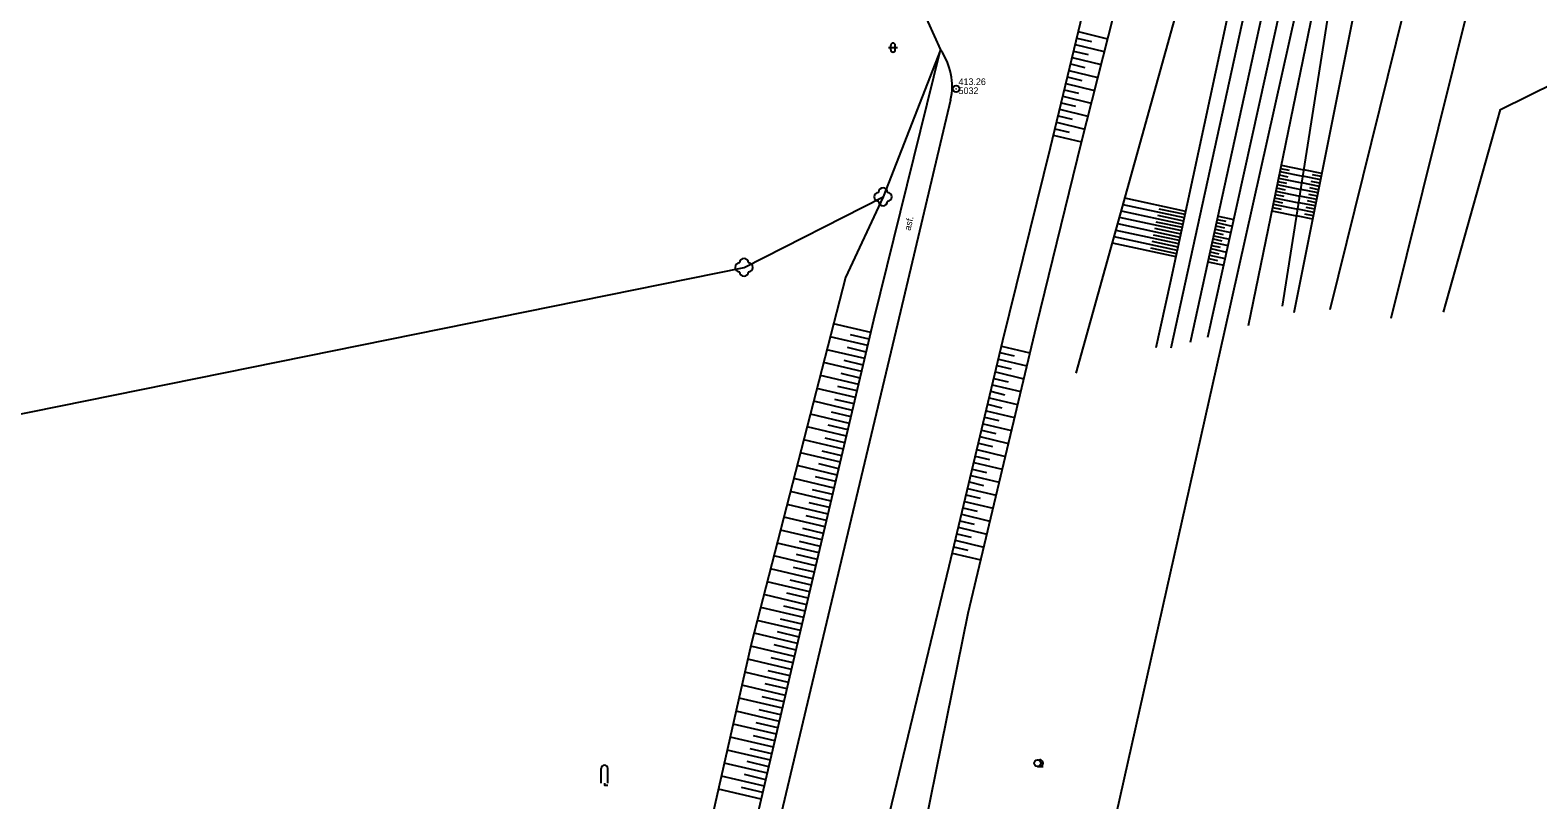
# Model space of a CAD drawing. Extents: x -737488 to -734267, y -1145775 to -1142573.
# Drawn here: x -734897.8 to -734727.9, y -1143098.1 to -1143011.4 of the extents above; entities that cross this region are included whole.
import ezdxf

# ---------------------------------------------------------------- set-up
doc = ezdxf.new("R2010")
doc.units = 0
for name, color, linetype in [('Vrstva 1', 7, 'Continuous'), ('Vrstva 10', 7, 'Continuous'), ('Vrstva 11', 7, 'Continuous'), ('Vrstva 12', 7, 'Continuous'), ('Vrstva 14', 7, 'Continuous'), ('Vrstva 19', 7, 'Continuous'), ('Vrstva 3', 7, 'Continuous'), ('Vrstva 9', 7, 'Continuous')]:
    doc.layers.add(name, color=color, linetype=linetype)

# ---------------------------------------------------------------- blocks, each defined once
blk = doc.blocks.new('1.079')
at = {"layer": 'Vrstva 1'}
for radius in [0.75, 0.001]:
    blk.add_circle((0, -0.001), radius, dxfattribs=at)
blk = doc.blocks.new('3.130')
at = {"layer": 'Vrstva 1'}
blk.add_circle((0, 0), 0.001, dxfattribs=at)
for centre, start, end in [((-1, 0), 90, 270), ((0, 1), 0, 180), ((1, 0), 270, 90), ((0, -1), 180, 360)]:
    blk.add_arc(centre, 1, start, end, dxfattribs=at)
blk = doc.blocks.new('3.100')
at = {"layer": 'Vrstva 1'}
for p, q in [((-0.75, 0), (-0.75, 3.25)), ((0.75, 0), (0.75, 3.25))]:
    blk.add_line(p, q, dxfattribs=at)
blk.add_lwpolyline([(0, 0), (0, -0.5), (0.75, -0.5)], dxfattribs=at)
blk.add_arc((0, 3.25), 0.75, 0, 180, dxfattribs=at)
blk = doc.blocks.new('3.110')
at = {"layer": 'Vrstva 1'}
blk.add_line((0, -0.75), (1.25, -0.75), dxfattribs=at)
blk.add_circle((0, 0), 0.75, dxfattribs=at)
blk.add_arc((0.5, 0), 0.75, 249.4944, 109.0474, dxfattribs=at)
blk = doc.blocks.new('3.160')
at = {"layer": 'Vrstva 1'}
for p, q in [((-1, 0), (1, 0)), ((-0.5, -0.5), (-0.5, 0.5)), ((0.5, -0.5), (0.5, 0.5))]:
    blk.add_line(p, q, dxfattribs=at)
for centre, start, end in [((0, 0.5), 0, 180), ((0, -0.5), 180, 360)]:
    blk.add_arc(centre, 0.5, start, end, dxfattribs=at)

msp = doc.modelspace()

# ---------------------------------------------------------------- linework, layer by layer
at = {"layer": 'Vrstva 10'}
for points in [[(-734751.34, -1143042.86), (-734739.27, -1142993.92), (-734731.29, -1142959.76)], [(-734744.49, -1143043.81), (-734732.04, -1142993.79), (-734723.59, -1142959.83)], [(-734782.88, -1143024.59), (-734776.82, -1142999.42)], [(-734799.53, -1143004.07), (-734795.25, -1143013.59)], [(-734802.76, -1143044), (-734795.25, -1143013.59)], [(-734794.12, -1143019.25), (-734800.11, -1143044.52)], [(-734788.23, -1143046.33), (-734782.88, -1143024.59)], [(-734811.45, -1143080.88), (-734802.76, -1143044)], [(-734800.11, -1143044.52), (-734808.87, -1143081.29)], [(-734794.3, -1143071.77), (-734788.23, -1143046.33)], [(-734800.43, -1143097.32), (-734794.3, -1143071.77)], [(-734821.67, -1143124.71), (-734811.45, -1143080.88)], [(-734808.87, -1143081.29), (-734819.27, -1143125.15)], [(-734806.53, -1143122.43), (-734800.43, -1143097.32)]]:
    msp.add_lwpolyline(points, dxfattribs=at)
msp.add_arc((-734801.12, -1143017.7), 7.17, 347.5402, 35.0408, dxfattribs=at)
at = {"layer": 'Vrstva 11'}
for points in [[(-734738.57, -1143043.16), (-734732.17, -1143020.29), (-734710.32, -1143009.52), (-734645.87, -1142991.4), (-734599.27, -1142980.03), (-734584.94, -1143004.15)], [(-734932.65, -1143097.27), (-734928.56, -1143060.61), (-734817.4, -1143038.1), (-734801.73, -1143030.15)]]:
    msp.add_lwpolyline(points, dxfattribs=at)
at = {"layer": 'Vrstva 12'}
for points in [[(-734779.96, -1143050.03), (-734764.08, -1142992.93), (-734756.15, -1142966.05), (-734753.33, -1142953.35)], [(-734770.94, -1143047.14), (-734769.33, -1143039.8), (-734750.72, -1142953.18)], [(-734767.1, -1143046.54), (-734757.95, -1143004.79), (-734746.58, -1142953.35)], [(-734765.15, -1143045.98), (-734756.07, -1143004.98), (-734744.15, -1142954.31)], [(-734760.57, -1143044.66), (-734752.72, -1143006.39), (-734741.14, -1142954.83)], [(-734756.74, -1143042.47), (-734751.11, -1143006.87), (-734739.76, -1142955.35)], [(-734755.41, -1143043.18), (-734747.78, -1143005.01), (-734735.87, -1142959.07)], [(-734779.39, -1143024), (-734770.86, -1142990.35)], [(-734779.74, -1143011.53), (-734776.43, -1143012.33)], [(-734795.25, -1143013.59), (-734801.73, -1143030.15), (-734805.97, -1143039.26)], [(-734780.26, -1143013.72), (-734778.62, -1143014.12)], [(-734780.09, -1143012.99), (-734776.8, -1143013.78)], [(-734779.91, -1143012.26), (-734778.26, -1143012.66)], [(-734780.62, -1143015.18), (-734778.98, -1143015.57)], [(-734780.44, -1143014.45), (-734777.17, -1143015.24)], [(-734780.97, -1143016.64), (-734779.34, -1143017.03)], [(-734780.79, -1143015.91), (-734777.54, -1143016.69)], [(-734781.49, -1143018.82), (-734778.27, -1143019.6)], [(-734781.32, -1143018.1), (-734779.7, -1143018.48)], [(-734781.14, -1143017.37), (-734777.91, -1143018.15)], [(-734781.84, -1143020.28), (-734778.64, -1143021.05)], [(-734781.67, -1143019.55), (-734780.06, -1143019.94)], [(-734782.19, -1143021.74), (-734779.01, -1143022.51)], [(-734782.02, -1143021.01), (-734780.42, -1143021.4)], [(-734784.45, -1143044.68), (-734779.39, -1143024)], [(-734782.55, -1143023.2), (-734779.38, -1143023.96)], [(-734782.37, -1143022.47), (-734780.78, -1143022.85)], [(-734757.01, -1143027.31), (-734754.43, -1143027.84)], [(-734756.94, -1143026.94), (-734755.96, -1143027.14)], [(-734756.86, -1143026.58), (-734754.31, -1143027.1)], [(-734752.28, -1143027.51), (-734754.31, -1143027.1)], [(-734757.39, -1143029.15), (-734756.41, -1143029.35)], [(-734757.31, -1143028.78), (-734754.66, -1143029.32)], [(-734757.24, -1143028.41), (-734756.26, -1143028.61)], [(-734757.16, -1143028.05), (-734754.54, -1143028.58)], [(-734757.09, -1143027.68), (-734756.11, -1143027.88)], [(-734752.57, -1143028.98), (-734754.54, -1143028.58)], [(-734752.42, -1143028.24), (-734754.43, -1143027.84)], [(-734752.65, -1143029.35), (-734753.63, -1143029.15)], [(-734752.5, -1143028.61), (-734753.48, -1143028.41)], [(-734752.35, -1143027.87), (-734753.33, -1143027.68)], [(-734767.61, -1143031.79), (-734774.48, -1143030.31)], [(-734757.69, -1143030.62), (-734756.71, -1143030.82)], [(-734757.61, -1143030.25), (-734754.9, -1143030.81)], [(-734757.54, -1143029.88), (-734756.56, -1143030.08)], [(-734757.46, -1143029.52), (-734754.78, -1143030.07)], [(-734753.01, -1143031.18), (-734754.9, -1143030.81)], [(-734752.87, -1143030.45), (-734754.78, -1143030.07)], [(-734752.72, -1143029.71), (-734754.66, -1143029.32)], [(-734752.94, -1143030.82), (-734753.92, -1143030.62)], [(-734752.79, -1143030.08), (-734753.77, -1143029.88)], [(-734768.08, -1143033.99), (-734775.08, -1143032.49)], [(-734767.92, -1143033.26), (-734774.88, -1143031.76)], [(-734767.77, -1143032.52), (-734774.68, -1143031.04)], [(-734767.85, -1143032.89), (-734770.78, -1143032.26)], [(-734767.69, -1143032.16), (-734770.62, -1143031.53)], [(-734763.99, -1143032.33), (-734762.21, -1143032.72)], [(-734757.92, -1143031.72), (-734755.13, -1143032.29)], [(-734757.84, -1143031.35), (-734756.86, -1143031.55)], [(-734757.77, -1143030.98), (-734755.01, -1143031.55)], [(-734753.31, -1143032.65), (-734755.13, -1143032.29)], [(-734753.16, -1143031.92), (-734755.01, -1143031.55)], [(-734753.23, -1143032.29), (-734754.21, -1143032.09)], [(-734753.09, -1143031.55), (-734754.07, -1143031.36)], [(-734768.4, -1143035.46), (-734775.48, -1143033.93)], [(-734768.24, -1143034.72), (-734775.28, -1143033.21)], [(-734768.16, -1143034.36), (-734771.09, -1143033.73)], [(-734768, -1143033.62), (-734770.94, -1143032.99)], [(-734764.39, -1143034.16), (-734763.41, -1143034.38)], [(-734764.31, -1143033.8), (-734762.54, -1143034.18)], [(-734764.23, -1143033.43), (-734763.25, -1143033.64)], [(-734764.15, -1143033.06), (-734762.38, -1143033.45)], [(-734764.07, -1143032.7), (-734763.09, -1143032.91)], [(-734768.71, -1143036.92), (-734775.89, -1143035.38)], [(-734768.55, -1143036.19), (-734775.69, -1143034.66)], [(-734768.63, -1143036.56), (-734771.57, -1143035.93)], [(-734768.48, -1143035.82), (-734771.41, -1143035.19)], [(-734768.32, -1143035.09), (-734771.25, -1143034.46)], [(-734764.71, -1143035.63), (-734763.73, -1143035.84)], [(-734764.63, -1143035.26), (-734762.86, -1143035.65)], [(-734764.55, -1143034.9), (-734763.57, -1143035.11)], [(-734764.47, -1143034.53), (-734762.7, -1143034.92)], [(-734765.11, -1143037.46), (-734763.35, -1143037.85)], [(-734765.03, -1143037.09), (-734764.05, -1143037.31)], [(-734764.95, -1143036.73), (-734763.19, -1143037.11)], [(-734764.87, -1143036.36), (-734763.89, -1143036.57)], [(-734764.79, -1143035.99), (-734763.02, -1143036.38)], [(-734805.97, -1143039.26), (-734816.58, -1143080.55)], [(-734803.45, -1143046.92), (-734807.68, -1143045.92)], [(-734803.1, -1143045.46), (-734807.31, -1143044.47)], [(-734803.28, -1143046.19), (-734805.39, -1143045.69)], [(-734792.16, -1143077.08), (-734784.45, -1143044.68)], [(-734803.79, -1143048.38), (-734808.06, -1143047.38)], [(-734803.62, -1143047.65), (-734805.74, -1143047.15)], [(-734788.56, -1143047.7), (-734786.95, -1143048.08)], [(-734788.38, -1143046.97), (-734785.18, -1143047.73)], [(-734804.14, -1143049.84), (-734808.43, -1143048.83)], [(-734803.96, -1143049.11), (-734806.1, -1143048.61)], [(-734788.9, -1143049.16), (-734787.3, -1143049.54)], [(-734788.73, -1143048.43), (-734785.52, -1143049.19)], [(-734804.48, -1143051.3), (-734808.8, -1143050.28)], [(-734804.31, -1143050.57), (-734806.46, -1143050.06)], [(-734789.25, -1143050.61), (-734787.65, -1143051)], [(-734789.08, -1143049.88), (-734785.87, -1143050.65)], [(-734804.82, -1143052.76), (-734809.18, -1143051.74)], [(-734804.65, -1143052.03), (-734806.82, -1143051.52)], [(-734789.77, -1143052.8), (-734786.57, -1143053.57)], [(-734789.6, -1143052.07), (-734788, -1143052.46)], [(-734789.43, -1143051.34), (-734786.22, -1143052.11)], [(-734805.17, -1143054.22), (-734809.55, -1143053.19)], [(-734805.34, -1143054.95), (-734807.54, -1143054.43)], [(-734805, -1143053.49), (-734807.18, -1143052.98)], [(-734790.12, -1143054.26), (-734786.91, -1143055.03)], [(-734789.95, -1143053.53), (-734788.34, -1143053.92)], [(-734805.86, -1143057.14), (-734810.3, -1143056.09)], [(-734805.51, -1143055.68), (-734809.92, -1143054.64)], [(-734805.68, -1143056.41), (-734807.9, -1143055.89)], [(-734790.47, -1143055.72), (-734787.26, -1143056.49)], [(-734790.3, -1143054.99), (-734788.69, -1143055.37)], [(-734806.2, -1143058.6), (-734810.67, -1143057.55)], [(-734806.03, -1143057.87), (-734808.26, -1143057.35)], [(-734790.99, -1143057.91), (-734789.39, -1143058.29)], [(-734790.82, -1143057.18), (-734787.61, -1143057.95)], [(-734790.65, -1143056.45), (-734789.04, -1143056.83)], [(-734806.54, -1143060.06), (-734811.04, -1143059)], [(-734806.37, -1143059.33), (-734808.61, -1143058.8)], [(-734791.34, -1143059.37), (-734789.73, -1143059.75)], [(-734791.17, -1143058.64), (-734787.95, -1143059.41)], [(-734806.89, -1143061.52), (-734811.42, -1143060.45)], [(-734806.72, -1143060.79), (-734808.97, -1143060.26)], [(-734791.69, -1143060.83), (-734790.08, -1143061.21)], [(-734791.52, -1143060.1), (-734788.3, -1143060.86)], [(-734807.23, -1143062.98), (-734811.79, -1143061.91)], [(-734807.06, -1143062.25), (-734809.33, -1143061.72)], [(-734792.21, -1143063.02), (-734789, -1143063.78)], [(-734792.04, -1143062.29), (-734790.43, -1143062.67)], [(-734791.86, -1143061.56), (-734788.65, -1143062.32)], [(-734807.92, -1143065.9), (-734812.54, -1143064.81)], [(-734807.58, -1143064.44), (-734812.16, -1143063.36)], [(-734807.75, -1143065.17), (-734810.05, -1143064.63)], [(-734807.4, -1143063.71), (-734809.69, -1143063.17)], [(-734792.56, -1143064.48), (-734789.34, -1143065.24)], [(-734792.39, -1143063.75), (-734790.78, -1143064.13)], [(-734808.26, -1143067.36), (-734812.91, -1143066.27)], [(-734808.09, -1143066.63), (-734810.41, -1143066.09)], [(-734792.91, -1143065.93), (-734789.69, -1143066.7)], [(-734792.73, -1143065.2), (-734791.13, -1143065.59)], [(-734808.61, -1143068.82), (-734813.28, -1143067.72)], [(-734808.44, -1143068.09), (-734810.77, -1143067.54)], [(-734793.43, -1143068.12), (-734791.82, -1143068.51)], [(-734793.26, -1143067.39), (-734790.04, -1143068.16)], [(-734793.08, -1143066.66), (-734791.47, -1143067.05)], [(-734808.95, -1143070.28), (-734813.66, -1143069.17)], [(-734808.78, -1143069.55), (-734811.13, -1143069)], [(-734793.78, -1143069.58), (-734792.17, -1143069.97)], [(-734793.6, -1143068.85), (-734790.39, -1143069.62)], [(-734809.3, -1143071.74), (-734814.03, -1143070.63)], [(-734809.12, -1143071.01), (-734811.48, -1143070.45)], [(-734793.95, -1143070.31), (-734790.73, -1143071.08)], [(-734809.64, -1143073.2), (-734814.4, -1143072.08)], [(-734809.47, -1143072.47), (-734811.84, -1143071.91)], [(-734810.33, -1143076.12), (-734815.15, -1143074.98)], [(-734809.98, -1143074.66), (-734814.78, -1143073.53)], [(-734810.16, -1143075.39), (-734812.56, -1143074.82)], [(-734809.81, -1143073.93), (-734812.2, -1143073.37)], [(-734810.67, -1143077.58), (-734815.52, -1143076.44)], [(-734810.5, -1143076.85), (-734812.92, -1143076.28)], [(-734811.02, -1143079.04), (-734815.9, -1143077.89)], [(-734810.85, -1143078.31), (-734813.28, -1143077.74)], [(-734800, -1143115.86), (-734792.16, -1143077.08)], [(-734811.36, -1143080.5), (-734816.27, -1143079.34)], [(-734811.19, -1143079.77), (-734813.64, -1143079.19)], [(-734816.58, -1143080.55), (-734824.34, -1143114.81)], [(-734811.7, -1143081.96), (-734816.64, -1143080.81)], [(-734811.53, -1143081.23), (-734814, -1143080.66)], [(-734812.04, -1143083.42), (-734816.97, -1143082.27)], [(-734811.87, -1143082.69), (-734814.34, -1143082.12)], [(-734812.72, -1143086.34), (-734817.63, -1143085.2)], [(-734812.38, -1143084.88), (-734817.3, -1143083.74)], [(-734812.55, -1143085.61), (-734815.01, -1143085.04)], [(-734812.21, -1143084.15), (-734814.67, -1143083.58)], [(-734813.07, -1143087.8), (-734817.96, -1143086.66)], [(-734812.89, -1143087.07), (-734815.35, -1143086.5)], [(-734813.41, -1143089.27), (-734818.3, -1143088.13)], [(-734813.24, -1143088.54), (-734815.68, -1143087.96)], [(-734813.75, -1143090.73), (-734818.63, -1143089.59)], [(-734813.58, -1143090), (-734816.02, -1143089.43)], [(-734814.09, -1143092.19), (-734818.96, -1143091.05)], [(-734813.92, -1143091.46), (-734816.35, -1143090.89)], [(-734814.43, -1143093.65), (-734819.29, -1143092.51)], [(-734814.26, -1143092.92), (-734816.69, -1143092.35)], [(-734814.77, -1143095.11), (-734819.62, -1143093.98)], [(-734814.94, -1143095.84), (-734817.36, -1143095.27)], [(-734814.6, -1143094.38), (-734817.03, -1143093.81)], [(-734815.45, -1143098.03), (-734820.28, -1143096.9)], [(-734815.11, -1143096.57), (-734819.95, -1143095.44)], [(-734815.28, -1143097.3), (-734817.7, -1143096.74)]]:
    msp.add_lwpolyline(points, dxfattribs=at)
at = {"layer": 'Vrstva 9'}
for points in [[(-734679.48, -1142673.32), (-734742.83, -1142954.66), (-734754.39, -1143005.54), (-734763.3, -1143045.45), (-734787.63, -1143153.95), (-734800.62, -1143211.35)], [(-734769.27, -1143047.16), (-734759.94, -1143004.57), (-734748.58, -1142952.88)]]:
    msp.add_lwpolyline(points, dxfattribs=at)

# ---------------------------------------------------------------- block references
at = {"layer": 'Vrstva 1', "xscale": 0.5, "yscale": 0.5}
msp.add_blockref('1.079', (-734793.5, -1143017.97), dxfattribs=at)
at = {"layer": 'Vrstva 11', "xscale": 0.5, "yscale": 0.5}
for p in [(-734801.73, -1143030.15), (-734817.4, -1143038.1)]:
    msp.add_blockref('3.130', p, dxfattribs=at)
at = {"layer": 'Vrstva 3', "xscale": 0.5, "yscale": 0.5}
for name, p in [('3.160', (-734800.61, -1143013.33)), ('3.110', (-734784.33, -1143093.98)), ('3.100', (-734833.13, -1143096.22))]:
    msp.add_blockref(name, p, dxfattribs=at)

# ---------------------------------------------------------------- texts
at = {"layer": 'Vrstva 14'}
msp.add_text('asf.', height=0.75, rotation=76.665, dxfattribs=at).set_placement((-734798.65, -1143034.01))
at = {"layer": 'Vrstva 19'}
for s, p in [(' 413.26', (-734793.5, -1143017.55)), (' 5032', (-734793.5, -1143018.57))]:
    msp.add_text(s, height=0.75, dxfattribs=at).set_placement(p)

doc.saveas('drawing.dxf')
